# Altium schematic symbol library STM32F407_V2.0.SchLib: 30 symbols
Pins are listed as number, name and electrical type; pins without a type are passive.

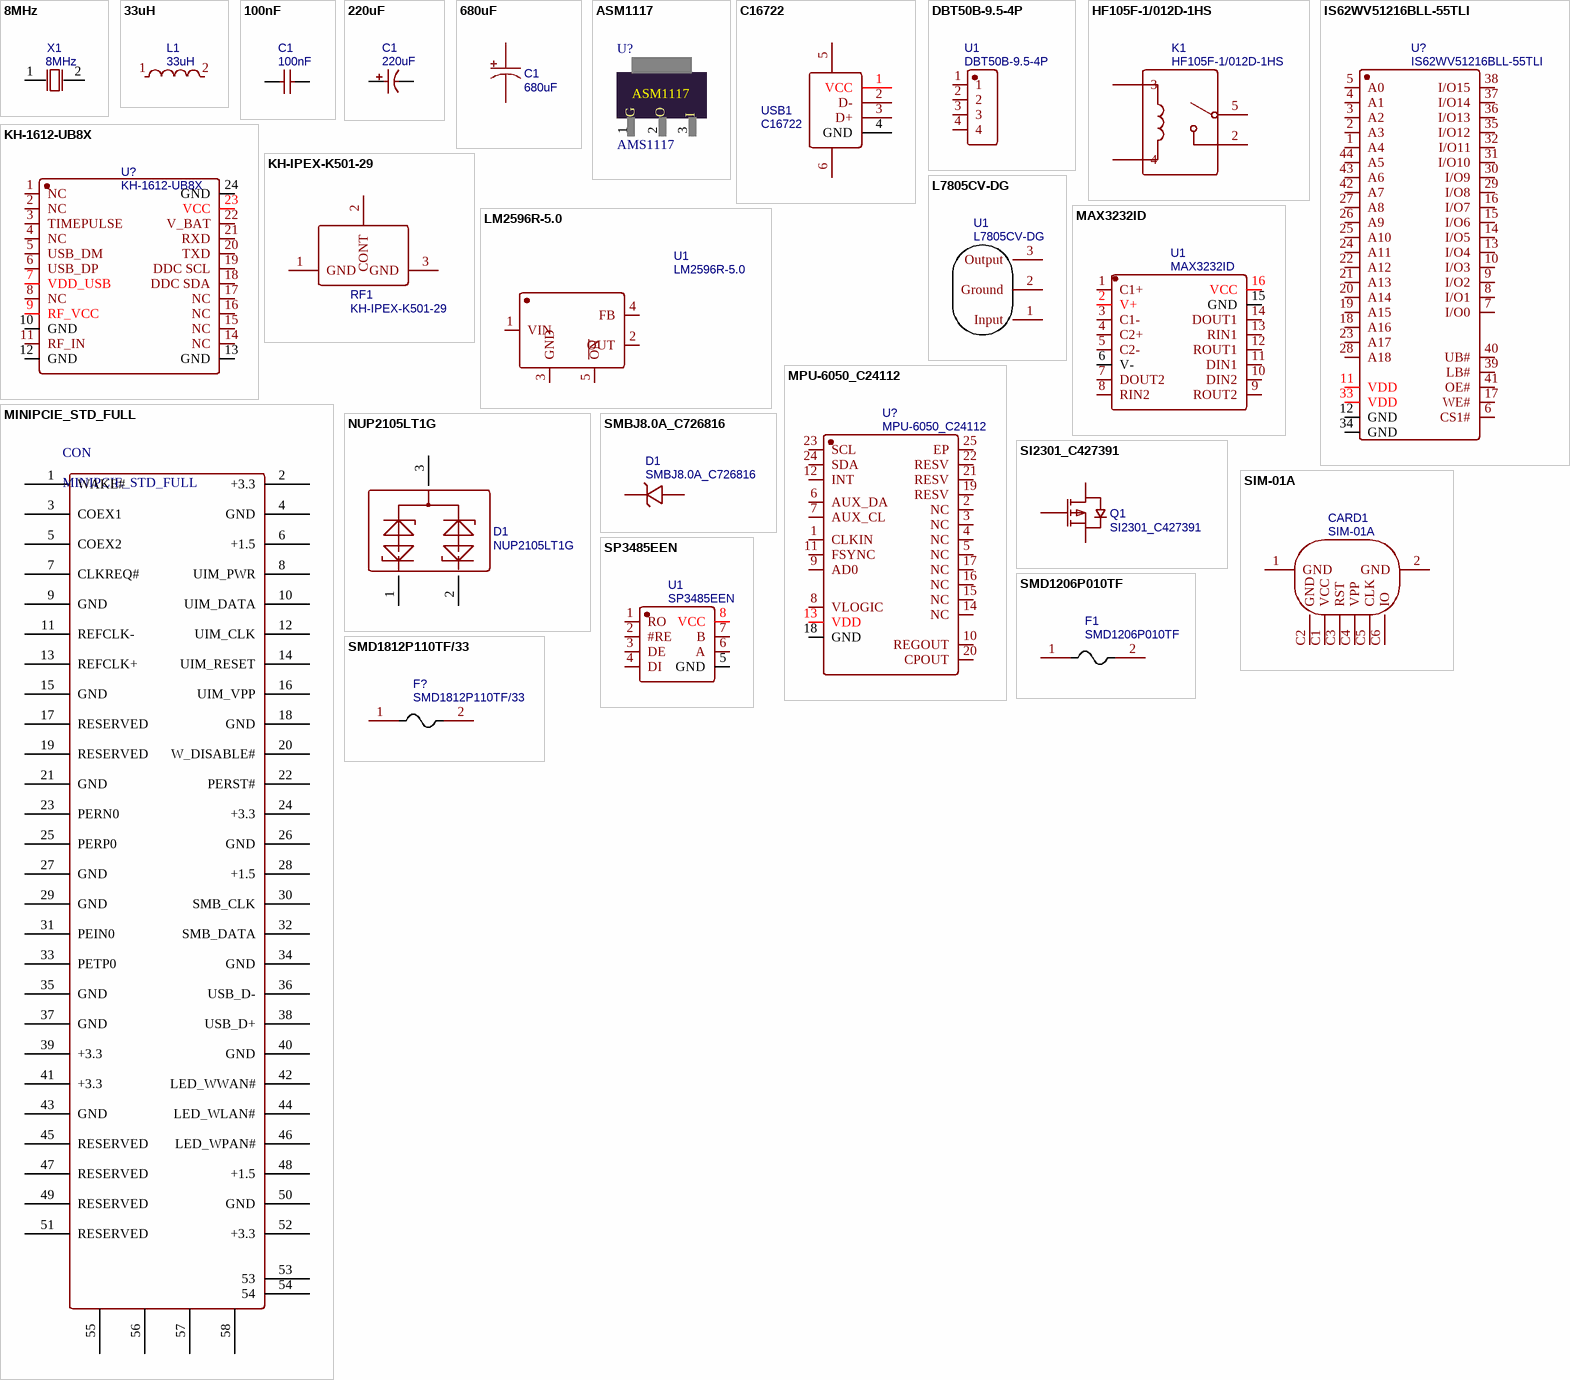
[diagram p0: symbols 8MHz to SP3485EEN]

## 8MHz
designator X1
贴片晶振; BOM_Manufacturer: TKD; BOM_Manufacturer Part: CS16M008000RD1; nameAlias: Frequency; Contributor: LCSC
footprint HC-49S_L11.4-W4.8
footprint HC-49S_L11.4-W4.8 (晶振8M)
pins: 1 OSC1, 2 OSC2

## 33uH
designator L1
BOM_Manufacturer: TDK; BOM_Manufacturer Part: SLF7045T-330MR82-PF; nameAlias: Inductance
footprint IND-SMD_L7.0-W6.8
pins: 1, 2

## 100nF
designator C1
BOM_Manufacturer: FH; BOM_Manufacturer Part: 1210B104K500NT; nameAlias: Capacitance
footprint C1210
pins: 1, 2

## 220uF
designator C1
BOM_Manufacturer: AISHI; BOM_Manufacturer Part: ERE1VM221F12OT; nameAlias: Capacitance
footprint CAP-TH_BD8.0-P3.50-D1.0-FD
pins: 1, 2

## 680uF
designator C1
BOM_Manufacturer: Ymin; BOM_Manufacturer Part: LKMD1601E681MF; nameAlias: Capacitance; Contributor: LCSC
footprint CAP-TH_BD8.0-P3.50-D1.0-FD
pins: 1, 2

## ASM1117
designator U?, comment AMS1117
footprint SOT-223_L6.7-W3.5-P2.30-BR
pins: 1, 2, 3

## C16722
designator USB1
USB_HOST; BOM_Manufacturer: Boom Precision Elec; Contributor: LCSC
footprint USB-A-TH_4P-V-F_13.7MM
footprint USB-A-TH_4P-V-F_13.7MM
pins: 1 VCC, 2 D-, 3 D+, 4 GND, 5 SH1, 6 SH2

## DBT50B-9.5-4P
designator U1
接线端子; BOM_Manufacturer: DIBO; Contributor: LCSC; BOM_Paste Type: expand
footprint CONN-TH_DBT50B-9.5-4P
footprint CONN-TH_DBT50B-9.5-4P
pins: 1, 2, 3, 4

## HF105F-1/012D-1HS
designator K1
继电器; BOM_Manufacturer: Xiamen Hongfa Electroacoustic; Contributor: LCSC; BOM_Paste Type: expand
footprint RELAY-TH_HF105F-XXX-1HXXX-XXX
footprint RELAY-TH_HF105F-XXX-1HXXX-XXX
pins: 2, 3, 4, 5

## IS62WV51216BLL-55TLI
designator U?
SRAM; BOM_Manufacturer: ISSI; BOM_Paste Type: recommend; BOM_Assembly Type: smtWeld; Rule: PcbType=ProtelPcb
footprint TSOP-44_L18.4-W10.2-P0.80-LS11.8-BL
pins: 1 A4, 2 A3, 3 A2, 4 A1, 5 A0, 6 CS1#, 7 I/O0, 8 I/O1, 9 I/O2, 10 I/O3, 11 VDD, 12 GND, 13 I/O4, 14 I/O5, 15 I/O6, 16 I/O7, 17 WE#, 18 A16, 19 A15, 20 A14, 21 A13, 22 A12, 23 A17, 24 A11, 25 A10, 26 A9, 27 A8, 28 A18, 29 I/O8, 30 I/O9, 31 I/O10, 32 I/O11, 33 VDD, 34 GND, 35 I/O12, 36 I/O13, 37 I/O14, 38 I/O15, 39 LB#, 40 UB#, 41 OE#, 42 A7, 43 A6, 44 A5

## KH-1612-UB8X
designator U?
GPS; BOM_Manufacturer: Shenzhen Kinghelm Elec; Contributor: LCSC
footprint GPSM-SMD_KH-1612-UBXX
pins: 1 NC, 2 NC, 3 TIMEPULSE, 4 NC, 5 USB_DM, 6 USB_DP, 7 VDD_USB, 8 NC, 9 RF_VCC, 10 GND, 11 RF_IN, 12 GND, 13 GND, 14 NC, 15 NC, 16 NC, 17 NC, 18 DDC SDA, 19 DDC SCL, 20 TXD, 21 RXD, 22 V_BAT, 23 VCC, 24 GND

## KH-IPEX-K501-29
designator RF1
天线插座; BOM_Manufacturer: Shenzhen Kinghelm Elec; Contributor: LCSC; BOM_Paste Type: expand
footprint ANT-SMD_KH-IPEX-K501-29
pins: 1 GND, 2 CONT, 3 GND

## L7805CV-DG
designator U1
BOM_Manufacturer: STMicroelectronics; BOM_Paste Type: expand
footprint TO-220-3_L10.0-W4.5-P2.54-L
pins: 1 Input, 2 Ground, 3 Output

## LM2596R-5.0
designator U1
BOM_Manufacturer: HTC
footprint TO-263-5_L10.2-W8.6-P1.70-LS14.4-TL
pins: 1 VIN, 2 OUT, 3 GND, 4 FB, 5 ~{ON}

## MAX3232ID
designator U1
BOM_Manufacturer: Texas Instruments; Contributor: LCSC; BOM_Paste Type: expand
footprint SOIC-16_L9.9-W3.9-P1.27-LS6.0-BL
pins: 1 C1+, 2 V+, 3 C1-, 4 C2+, 5 C2-, 6 V-, 7 DOUT2, 8 RIN2, 9 ROUT2, 10 DIN2, 11 DIN1, 12 ROUT1, 13 RIN1, 14 DOUT1, 15 GND, 16 VCC

## MINIPCIE_STD_FULL
designator CON
4G插座
footprint MINI_PCISHM
pins: 1 WAKE#, 2 +3.3, 3 COEX1, 4 GND, 5 COEX2, 6 +1.5, 7 CLKREQ#, 8 UIM_PWR, 9 GND, 10 UIM_DATA, 11 REFCLK-, 12 UIM_CLK, 13 REFCLK+, 14 UIM_RESET, 15 GND, 16 UIM_VPP, 17 RESERVED, 18 GND, 19 RESERVED, 20 W_DISABLE#, 21 GND, 22 PERST#, 23 PERN0, 24 +3.3, 25 PERP0, 26 GND, 27 GND, 28 +1.5, 29 GND, 30 SMB_CLK, 31 PEIN0, 32 SMB_DATA, 33 PETP0, 34 GND, 35 GND, 36 USB_D-, 37 GND, 38 USB_D+, 39 +3.3, 40 GND, 41 +3.3, 42 LED_WWAN#, 43 GND, 44 LED_WLAN#, 45 RESERVED, 46 LED_WPAN#, 47 RESERVED, 48 +1.5, 49 RESERVED, 50 GND, 51 RESERVED, 52 +3.3, 53, 54, 55, 56, 57, 58

## MPU-6050_C24112
designator U?
陀螺仪; BOM_Manufacturer: InvenSense; sourceId: 1T5FDZYC8; BOM_Paste Type: base
footprint QFN-24_L4.0-W4.0-P0.50-BL-EP2.6
pins: 1 CLKIN, 2 NC, 3 NC, 4 NC, 5 NC, 6 AUX_DA, 7 AUX_CL, 8 VLOGIC, 9 AD0, 10 REGOUT, 11 FSYNC, 12 INT, 13 VDD, 14 NC, 15 NC, 16 NC, 17 NC, 18 GND, 19 RESV, 20 CPOUT, 21 RESV, 22 RESV, 23 SCL, 24 SDA, 25 EP

## NUP2105LT1G
designator D1
BOM_Manufacturer: ON; BOM_Paste Type: expand
footprint SOT-23-3_L2.9-W1.6-P1.90-LS2.8-BR
pins: 1, 2, 3

## SI2301_C427391
designator Q1
BOM_Manufacturer: MDD（Microdiode Electronics）; BOM_Manufacturer Part: SI2301; Contributor: LCSC
footprint SOT-23-3_L2.9-W1.3-P1.90-LS2.4-BR
pins: 1 G, 2 S, 3 D

## SIM-01A
designator CARD1
BOM_Manufacturer: HRO
footprint SIM-SMD_SIM-01A
pins: 1 GND, 2 GND, C1 VCC, C2 GND, C3 RST, C4 VPP, C5 CLK, C6 IO

## SMBJ8.0A_C726816
designator D1
BOM_Manufacturer: TWGMC; Contributor: LCSC
footprint SMB_L4.6-W3.6-LS5.3-RD
pins: 1, 2

## SMD1206P010TF
designator F1
BOM_Manufacturer: RUILON; BOM_Paste Type: recommend
footprint F1206
pins: 1, 2

## SMD1812P110TF/33
designator F?
保险丝; BOM_Manufacturer: RUILON; BOM_Paste Type: expand
footprint F1812
pins: 1, 2

## SP3485EEN
designator U1
BOM_Manufacturer: UMW(Youtai Semiconductor Co., Ltd.); Contributor: LCSC; BOM_Paste Type: expand
footprint SOP-8_L5.0-W4.0-P1.27-LS6.0-BL
pins: 1 RO, 2 #RE, 3 DE, 4 DI, 5 GND, 6 A, 7 B, 8 VCC

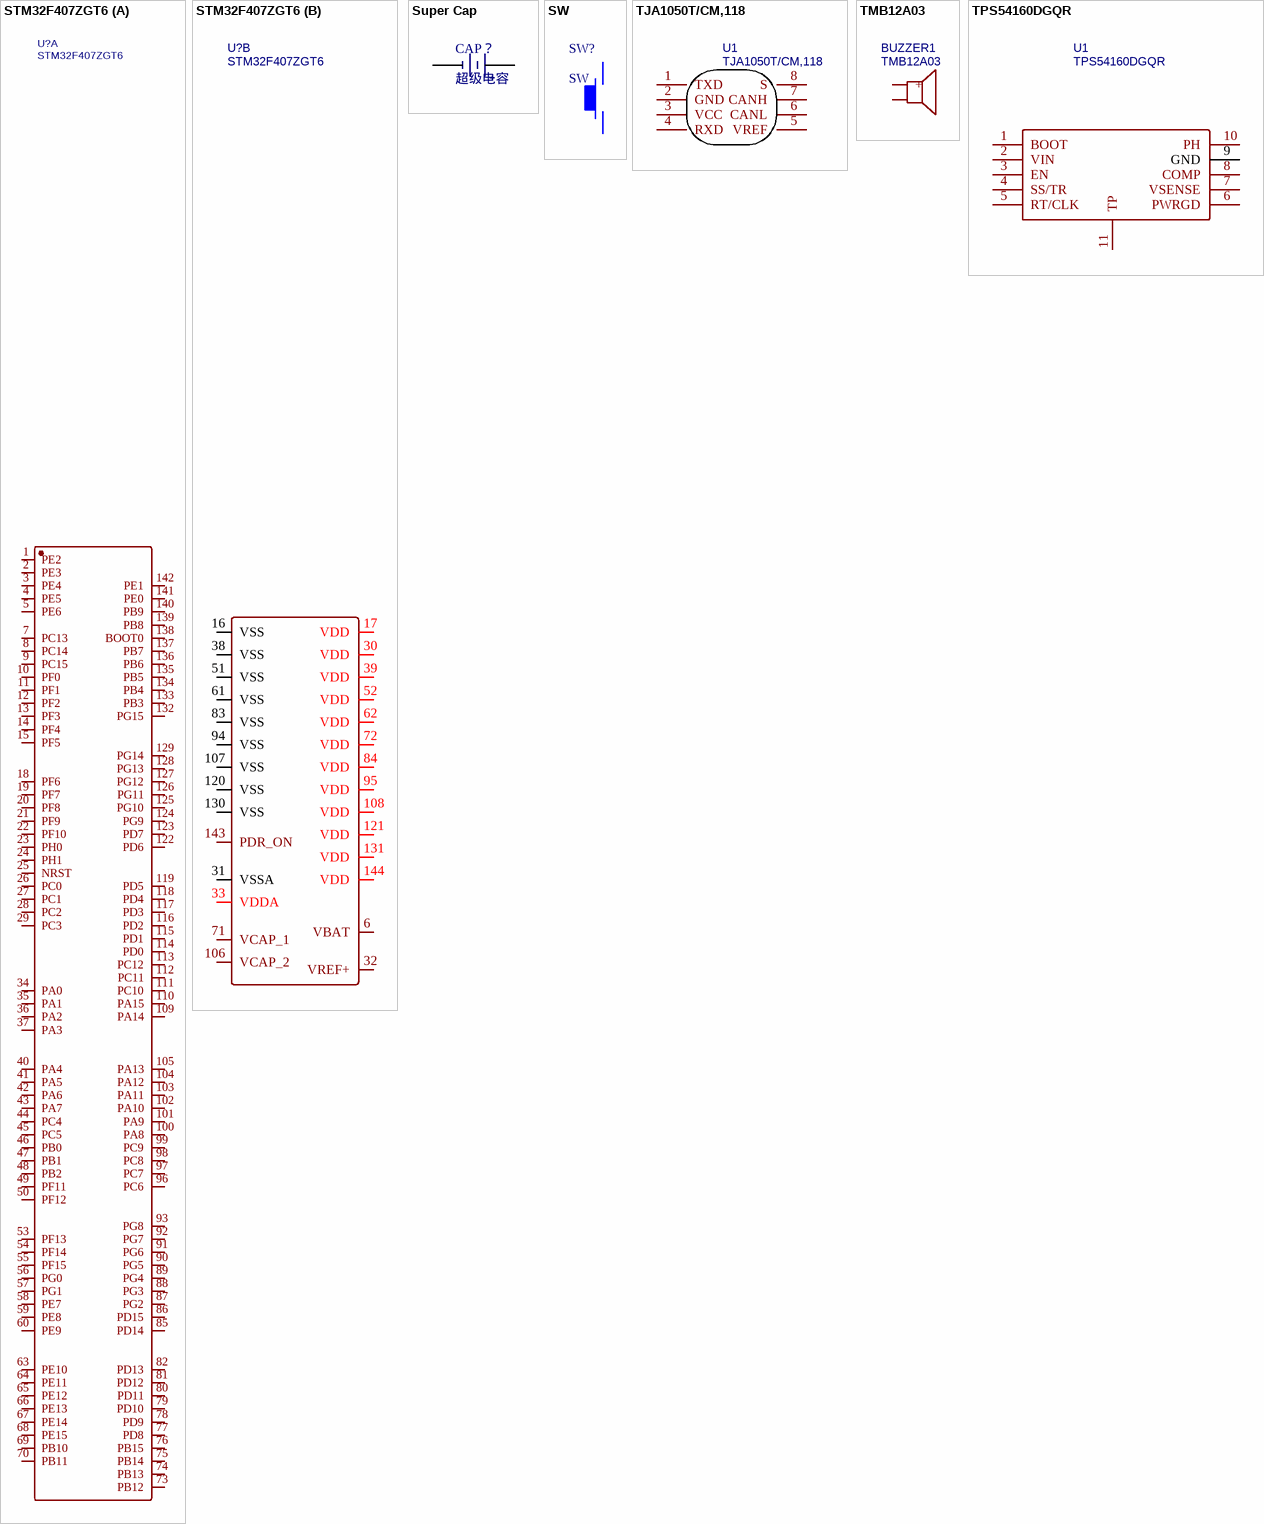
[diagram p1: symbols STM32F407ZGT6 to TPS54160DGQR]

## STM32F407ZGT6
designator U?
MCU; BOM_Manufacturer: ST; subpart_no: 1; tags: STM32; BOM_Paste Type: recommend; BOM_Assembly Type: smtWeld
footprint LQFP-144_L20.0-W20.0-P0.50-LS22.0-BL
part A pins: 1 PE2, 2 PE3, 3 PE4, 4 PE5, 5 PE6, 7 PC13, 8 PC14, 9 PC15, 10 PF0, 11 PF1, 12 PF2, 13 PF3, 14 PF4, 15 PF5, 18 PF6, 19 PF7, 20 PF8, 21 PF9, 22 PF10, 23 PH0, 24 PH1, 25 NRST, 26 PC0, 27 PC1, 28 PC2, 29 PC3, 34 PA0, 35 PA1, 36 PA2, 37 PA3, 40 PA4, 41 PA5, 42 PA6, 43 PA7, 44 PC4, 45 PC5, 46 PB0, 47 PB1, 48 PB2, 49 PF11, 50 PF12, 53 PF13, 54 PF14, 55 PF15, 56 PG0, 57 PG1, 58 PE7, 59 PE8, 60 PE9, 63 PE10, 64 PE11, 65 PE12, 66 PE13, 67 PE14, 68 PE15, 69 PB10, 70 PB11, 73 PB12, 74 PB13, 75 PB14, 76 PB15, 77 PD8, 78 PD9, 79 PD10, 80 PD11, 81 PD12, 82 PD13, 85 PD14, 86 PD15, 87 PG2, 88 PG3, 89 PG4, 90 PG5, 91 PG6, 92 PG7, 93 PG8, 96 PC6, 97 PC7, 98 PC8, 99 PC9, 100 PA8, 101 PA9, 102 PA10, 103 PA11, 104 PA12, 105 PA13, 109 PA14, 110 PA15, 111 PC10, 112 PC11, 113 PC12, 114 PD0, 115 PD1, 116 PD2, 117 PD3, 118 PD4, 119 PD5, 122 PD6, 123 PD7, 124 PG9, 125 PG10, 126 PG11, 127 PG12, 128 PG13, 129 PG14, 132 PG15, 133 PB3, 134 PB4, 135 PB5, 136 PB6, 137 PB7, 138 BOOT0, 139 PB8, 140 PB9, 141 PE0, 142 PE1
part B pins: 6 VBAT, 16 VSS, 17 VDD, 30 VDD, 31 VSSA, 32 VREF+, 33 VDDA, 38 VSS, 39 VDD, 51 VSS, 52 VDD, 61 VSS, 62 VDD, 71 VCAP_1, 72 VDD, 83 VSS, 84 VDD, 94 VSS, 95 VDD, 106 VCAP_2, 107 VSS, 108 VDD, 120 VSS, 121 VDD, 130 VSS, 131 VDD, 143 PDR_ON, 144 VDD

## Super Cap
designator CAP？, comment 超级电容
footprint CAP-TH_XH414HG
pins: 1, 2

## SW
designator SW?
footprint SW-TH_4P-L6.0-W6.0-P4.50-LS6.5
pins: 1, 3

## TJA1050T/CM,118
designator U1
BOM_Manufacturer: NXP; BOM_Paste Type: base
footprint SOIC-8_L5.0-W4.0-P1.27-LS6.0-BL
pins: 1 TXD, 2 GND, 3 VCC, 4 RXD, 5 VREF, 6 CANL, 7 CANH, 8 S

## TMB12A03
designator BUZZER1
蜂鸣器; BOM_Manufacturer: HNDZ; BOM_Paste Type: expand; BOM_Assembly Type: manualWeld
footprint BUZ-TH_BD12.0-P7.60-D0.6-FD
footprint BUZ-TH_BD12.0-P7.60-D0.6-FD
pins: 1 +, 2

## TPS54160DGQR
designator U1
BOM_Manufacturer: TI; BOM_Paste Type: expand
footprint MSOP-10_L3.0-W3.0-P0.50-LS5.0-BL-EP
pins: 1 BOOT, 2 VIN, 3 EN, 4 SS/TR, 5 RT/CLK, 6 PWRGD, 7 VSENSE, 8 COMP, 9 GND, 10 PH, 11 TP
